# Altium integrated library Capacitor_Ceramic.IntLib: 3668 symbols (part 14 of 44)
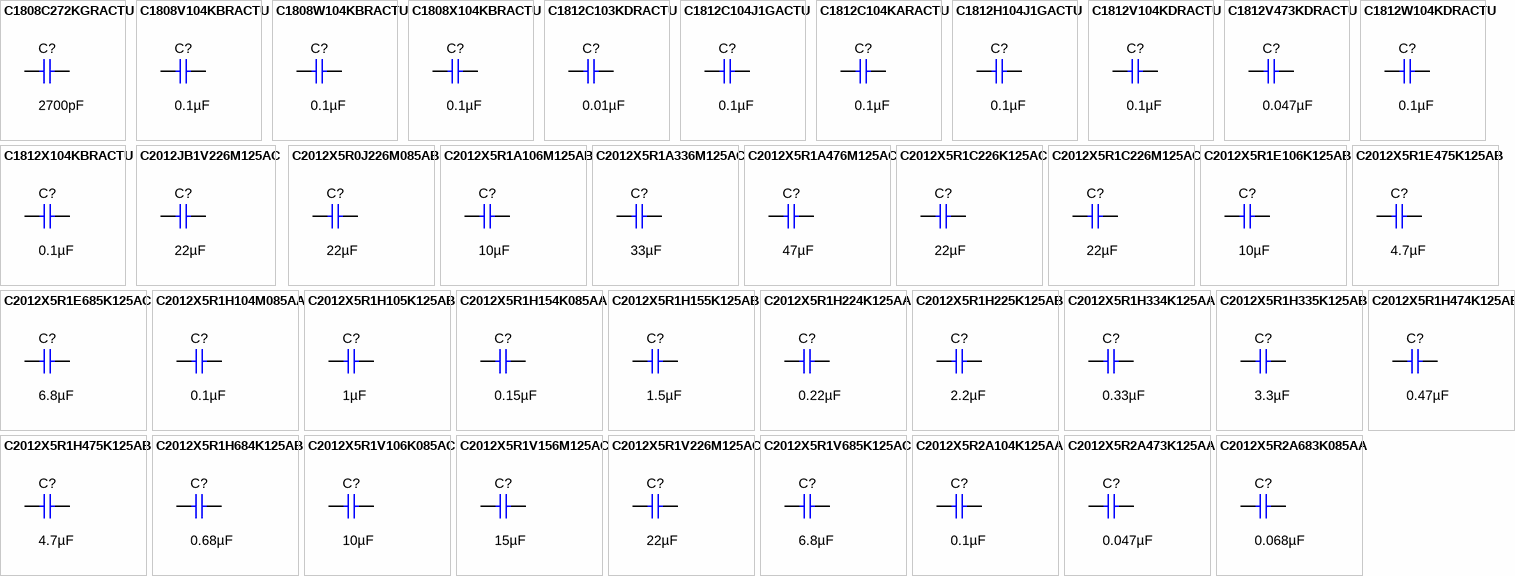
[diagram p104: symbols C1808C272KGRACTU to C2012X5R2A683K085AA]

## C1808V104KBRACTU
designator C?  ValueDisplayed: 0.1µF  (hidden comment: C1808V104KBRACTU)
CAP, CERM, 0.1 µF, 630 V,+/- 10%, X7R, 1808; Manufacturer: Kemet; Polarized: N; CompType: Capacitor; Value: 0.1uF; U/M: EA; Cap_F: 0.0000001; Tolerance_%: 10; VDC_V: 630; Value2: 630V; TaMin_C: -55; TaMax_C: 125; Cap_Case: 1808; SizeArea_mm2: 9; SizeAreaWB_mm2: 16.5; SizeX_mm: 4.5; SizeY_mm: 2; SizeZ_mm: 2.15; AEC Category: Q200; Green_Lifecycle: Not Set; Green_REACh: Incomplete
signal-integrity model Cap
simulation model Cap
footprint 1808_215
footprint 1808_215_M
footprint 1808_215_L
pins: 1, 2

## C1808W104KBRACTU
designator C?  ValueDisplayed: 0.1µF  (hidden comment: C1808W104KBRACTU)
CAP, CERM, 0.1 µF, 630 V,+/- 10%, X7R, 1808; Manufacturer: Kemet; Polarized: N; CompType: Capacitor; Value: 0.1uF; U/M: EA; Cap_F: 0.0000001; Tolerance_%: 10; VDC_V: 630; Value2: 630V; TaMin_C: -55; TaMax_C: 125; Cap_Case: 1808; SizeArea_mm2: 9; SizeAreaWB_mm2: 16.5; SizeX_mm: 4.5; SizeY_mm: 2; SizeZ_mm: 2.15; AEC Category: Q200; Green_Lifecycle: Not Set; Green_REACh: Incomplete
signal-integrity model Cap
simulation model Cap
footprint 1808_215
footprint 1808_215_M
footprint 1808_215_L
pins: 1, 2

## C1808X104KBRACTU
designator C?  ValueDisplayed: 0.1µF  (hidden comment: C1808X104KBRACTU)
CAP, CERM, 0.1 µF, 630 V,+/- 10%, X7R, 1808; Manufacturer: Kemet; Polarized: N; CompType: Capacitor; Value: 0.1uF; U/M: EA; Cap_F: 0.0000001; Tolerance_%: 10; VDC_V: 630; Value2: 630V; TaMin_C: -55; TaMax_C: 125; Cap_Case: 1808; SizeArea_mm2: 9; SizeAreaWB_mm2: 16.5; SizeX_mm: 4.5; SizeY_mm: 2; SizeZ_mm: 2.15; AEC Category: Q200; Green_Lifecycle: Not Set; Green_REACh: Incomplete
signal-integrity model Cap
simulation model Cap
footprint 1808_215
footprint 1808_215_M
footprint 1808_215_L
pins: 1, 2

## C1812C103KDRACTU
designator C?  ValueDisplayed: 0.01µF  (hidden comment: C1812C103KDRACTU)
CAP, CERM, 0.01 µF, 1000 V,+/- 10%, X7R, 1812; Manufacturer: Kemet; Polarized: N; CompType: Capacitor; Value: 0.01uF; U/M: EA; Cap_F: 0.00000001; Tolerance_%: 10; VDC_V: 1000; Value2: 1000V; TaMin_C: -55; TaMax_C: 125; Cap_Case: 1812; SizeArea_mm2: 14.4; SizeAreaWB_mm2: 23.1; SizeX_mm: 4.5; SizeY_mm: 3.2; SizeZ_mm: 1.8; AEC Category: Q200; Green_Lifecycle: Not Set; Green_REACh: Incomplete
signal-integrity model Cap
simulation model Cap
footprint 1812_180
pins: 1, 2

## C1812C104J1GACTU
designator C?  ValueDisplayed: 0.1µF  (hidden comment: C1812C104J1GACTU)
CAP, CERM, 0.1 µF, 100 V,+/- 5%, C0G/NP0, 1812; Manufacturer: Kemet; Polarized: N; CompType: Capacitor; Value: 0.1uF; U/M: EA; Cap_F: 0.0000001; Tolerance_%: 5; VDC_V: 100; Value2: 100V; TaMin_C: -55; TaMax_C: 125; Cap_Case: 1812; SizeArea_mm2: 14.4; SizeAreaWB_mm2: 23.1; SizeX_mm: 4.5; SizeY_mm: 3.2; SizeZ_mm: 1.35; AEC Category: Q200; Green_Lifecycle: Active; Green_REACh: Passed
signal-integrity model Cap
simulation model Cap
footprint 1812
footprint 1812M
footprint 1812L
footprint 1812_HV
pins: 1, 2

## C1812C104KARACTU
designator C?  ValueDisplayed: 0.1µF  (hidden comment: C1812C104KARACTU)
CAP, CERM, 0.1 µF, 250 V,+/- 10%, X7R, 1812; Manufacturer: Kemet; Polarized: N; CompType: Capacitor; Value: 0.1uF; U/M: EA; Cap_F: 0.0000001; Tolerance_%: 10; VDC_V: 250; Value2: 250V; TaMin_C: -55; TaMax_C: 125; Cap_Case: 1812; SizeArea_mm2: 14.4; SizeAreaWB_mm2: 23.1; SizeX_mm: 4.5; SizeY_mm: 3.2; SizeZ_mm: 1.35; AEC Category: Q200
signal-integrity model Cap
simulation model Cap
footprint 1812
footprint 1812M
footprint 1812L
footprint 1812_HV
pins: 1, 2

## C1812H104J1GACTU
designator C?  ValueDisplayed: 0.1µF  (hidden comment: C1812H104J1GACTU)
CAP, CERM, 0.1 µF, 100 V,+/- 5%, C0G/NP0, 1812; Manufacturer: Kemet; Polarized: N; CompType: Capacitor; Value: 0.1uF; U/M: EA; Cap_F: 0.0000001; Tolerance_%: 5; VDC_V: 100; Value2: 100V; TaMin_C: -55; TaMax_C: 200; Cap_Case: 1812; SizeArea_mm2: 14.4; SizeAreaWB_mm2: 23.1; SizeX_mm: 4.5; SizeY_mm: 3.2; SizeZ_mm: 1.35; AEC Category: Q200
signal-integrity model Cap
simulation model Cap
footprint 1812
footprint 1812M
footprint 1812L
footprint 1812_HV
pins: 1, 2

## C1812V104KDRACTU
designator C?  ValueDisplayed: 0.1µF  (hidden comment: C1812V104KDRACTU)
CAP, CERM, 0.1 µF, 1000 V,+/- 10%, X7R, 1812; Manufacturer: Kemet; Polarized: N; CompType: Capacitor; Value: 0.1uF; U/M: EA; Cap_F: 0.0000001; Tolerance_%: 10; VDC_V: 1000; Value2: 1000V; TaMin_C: -55; TaMax_C: 125; Cap_Case: 1812; SizeArea_mm2: 14.4; SizeAreaWB_mm2: 23.1; SizeX_mm: 4.5; SizeY_mm: 3.2; SizeZ_mm: 2.54; AEC Category: Q200; Green_Lifecycle: Not Set; Green_REACh: Incomplete
signal-integrity model Cap
simulation model Cap
footprint 1812_254
pins: 1, 2

## C1812V473KDRACTU
designator C?  ValueDisplayed: 0.047µF  (hidden comment: C1812V473KDRACTU)
CAP, CERM, 0.047 µF, 1000 V,+/- 10%, X7R, 1812; Manufacturer: Kemet; Polarized: N; CompType: Capacitor; Value: 0.047uF; U/M: EA; Cap_F: 0.000000047; Tolerance_%: 10; VDC_V: 1000; Value2: 1000V; TaMin_C: -55; TaMax_C: 125; Cap_Case: 1812; SizeArea_mm2: 14.4; SizeAreaWB_mm2: 23.1; SizeX_mm: 4.5; SizeY_mm: 3.2; SizeZ_mm: 1.35; AEC Category: Q200
signal-integrity model Cap
simulation model Cap
footprint 1812
footprint 1812M
footprint 1812L
footprint 1812_HV
pins: 1, 2

## C1812W104KDRACTU
designator C?  ValueDisplayed: 0.1µF  (hidden comment: C1812W104KDRACTU)
CAP, CERM, 0.1 µF, 1000 V,+/- 10%, X7R, 1812; Manufacturer: Kemet; Polarized: N; CompType: Capacitor; Value: 0.1uF; U/M: EA; Cap_F: 0.0000001; Tolerance_%: 10; VDC_V: 1000; Value2: 1000V; TaMin_C: -55; TaMax_C: 125; Cap_Case: 1812; SizeArea_mm2: 14.4; SizeAreaWB_mm2: 23.1; SizeX_mm: 4.5; SizeY_mm: 3.2; SizeZ_mm: 2.54; AEC Category: Q200; Green_Lifecycle: Active; Green_REACh: Passed
signal-integrity model Cap
simulation model Cap
footprint 1812_254
pins: 1, 2

## C1812X104KBRACTU
designator C?  ValueDisplayed: 0.1µF  (hidden comment: C1812X104KBRACTU)
CAP, CERM, 0.1 µF, 630 V,+/- 10%, X7R, 1812; Manufacturer: Kemet; Polarized: N; CompType: Capacitor; Value: 0.1uF; U/M: EA; Cap_F: 0.0000001; Tolerance_%: 10; VDC_V: 630; Value2: 630V; TaMin_C: -55; TaMax_C: 125; Cap_Case: 1812; SizeArea_mm2: 14.4; SizeAreaWB_mm2: 23.1; SizeX_mm: 4.5; SizeY_mm: 3.2; SizeZ_mm: 2.54; AEC Category: Q200; Green_Lifecycle: Not Set; Green_REACh: Incomplete
signal-integrity model Cap
simulation model Cap
footprint 1812_254
pins: 1, 2

## C2012JB1V226M125AC
designator C?  ValueDisplayed: 22µF  (hidden comment: C2012JB1V226M125AC)
CAP, CERM, 22 µF, 35 V,+/- 20%, JB, 0805; Manufacturer: TDK; Polarized: N; CompType: Capacitor; Value: 22uF; U/M: EA; Cap_F: 0.000022; Tolerance_%: 20; VDC_V: 35; Value2: 35V; TaMin_C: -25; TaMax_C: 85; Cap_Case: 0805; SizeArea_mm2: 2.5; SizeAreaWB_mm2: 6.75; SizeX_mm: 2; SizeY_mm: 1.25; SizeZ_mm: 1.45; AEC Category: Q200; Green_Lifecycle: Active; Green_REACh: Passed
signal-integrity model Cap
simulation model Cap
footprint 0805_HV
footprint 0805_HV1
footprint 0805
footprint 0805M
footprint 0805L
pins: 1, 2

## C2012X5R0J226M085AB
designator C?  ValueDisplayed: 22µF  (hidden comment: C2012X5R0J226M085AB)
CAP, CERM, 22 µF, 6.3 V,+/- 20%, X5R, 0805; Manufacturer: TDK; Polarized: N; CompType: Capacitor; Value: 22uF; U/M: EA; Cap_F: 0.000022; Tolerance_%: 20; VDC_V: 6.3; Value2: 6.3V; TaMin_C: -55; TaMax_C: 85; Cap_Case: 0805; SizeArea_mm2: 2.5; SizeAreaWB_mm2: 6.75; SizeX_mm: 2; SizeY_mm: 1.25; SizeZ_mm: 1.45; AEC Category: Q200
signal-integrity model Cap
simulation model Cap
footprint 0805_HV
footprint 0805_HV1
footprint 0805
footprint 0805M
footprint 0805L
pins: 1, 2

## C2012X5R1A106M125AB
designator C?  ValueDisplayed: 10µF  (hidden comment: C2012X5R1A106M125AB)
CAP, CERM, 10 µF, 10 V,+/- 20%, X5R, 0805; Manufacturer: TDK; Polarized: N; CompType: Capacitor; Value: 10uF; U/M: EA; Cap_F: 0.00001; Tolerance_%: 20; VDC_V: 10; Value2: 10V; TaMin_C: -55; TaMax_C: 85; Cap_Case: 0805; SizeArea_mm2: 2.5; SizeAreaWB_mm2: 6.75; SizeX_mm: 2; SizeY_mm: 1.25; SizeZ_mm: 1.5; AEC Category: Q200; Green_Lifecycle: EOL; Green_REACh: Passed
signal-integrity model Cap
simulation model Cap
footprint 0805_150
pins: 1, 2

## C2012X5R1A336M125AC
designator C?  ValueDisplayed: 33µF  (hidden comment: C2012X5R1A336M125AC)
CAP, CERM, 33 µF, 10 V,+/- 20%, X5R, 0805; Manufacturer: TDK; Polarized: N; CompType: Capacitor; Value: 33uF; U/M: EA; Cap_F: 0.000033; Tolerance_%: 20; ESR_ohm: 0.001694; Value1: 0.001694 ohm; VDC_V: 10; Value2: 10V; IRMS_A: 5.01281; TaMin_C: -55; TaMax_C: 85; Cap_Case: 0805; SizeArea_mm2: 2.5; SizeAreaWB_mm2: 6.75; SizeX_mm: 2; SizeY_mm: 1.25; SizeZ_mm: 1.45; AEC Category: Q200; Green_Lifecycle: Active; Green_REACh: Passed
signal-integrity model Cap
simulation model Cap
footprint 0805_HV
footprint 0805_HV1
footprint 0805
footprint 0805M
footprint 0805L
pins: 1, 2

## C2012X5R1A476M125AC
designator C?  ValueDisplayed: 47µF  (hidden comment: C2012X5R1A476M125AC)
CAP, CERM, 47 µF, 10 V,+/- 20%, X5R, 0805; Manufacturer: TDK; Polarized: N; CompType: Capacitor; Value: 47uF; U/M: EA; Cap_F: 0.000047; Tolerance_%: 20; ESR_ohm: 0.00294; Value1: 0.00294 ohm; VDC_V: 10; Value2: 10V; IRMS_A: 3.80451; TaMin_C: -55; TaMax_C: 85; Cap_Case: 0805; SizeArea_mm2: 2.5; SizeAreaWB_mm2: 6.75; SizeX_mm: 2; SizeY_mm: 1.25; SizeZ_mm: 1.45; AEC Category: Q200; Green_Lifecycle: Active; Green_REACh: Passed
signal-integrity model Cap
simulation model Cap
footprint 0805_HV
footprint 0805_HV1
footprint 0805
footprint 0805M
footprint 0805L
pins: 1, 2

## C2012X5R1C226K125AC
designator C?  ValueDisplayed: 22µF  (hidden comment: C2012X5R1C226K125AC)
CAP, CERM, 22 µF, 16 V,+/- 10%, X5R, 0805; Manufacturer: TDK; Polarized: N; CompType: Capacitor; Value: 22uF; U/M: EA; Cap_F: 0.000022; Tolerance_%: 10; VDC_V: 16; Value2: 16V; TaMin_C: -55; TaMax_C: 85; Cap_Case: 0805; SizeArea_mm2: 2.5; SizeAreaWB_mm2: 6.75; SizeX_mm: 2; SizeY_mm: 1.25; SizeZ_mm: 1.45; AEC Category: Q200; Green_Lifecycle: Active; Green_REACh: Passed
signal-integrity model Cap
simulation model Cap
footprint 0805_HV
footprint 0805_HV1
footprint 0805
footprint 0805M
footprint 0805L
pins: 1, 2

## C2012X5R1C226M125AC
designator C?  ValueDisplayed: 22µF  (hidden comment: C2012X5R1C226M125AC)
CAP, CERM, 22 µF, 16 V,+/- 20%, X5R, 0805; Manufacturer: TDK; Polarized: N; CompType: Capacitor; Value: 22uF; U/M: EA; Cap_F: 0.000022; Tolerance_%: 20; VDC_V: 16; Value2: 16V; TaMin_C: -55; TaMax_C: 85; Cap_Case: 0805; SizeArea_mm2: 2.5; SizeAreaWB_mm2: 6.75; SizeX_mm: 2; SizeY_mm: 1.25; SizeZ_mm: 1.45; AEC Category: Q200; Green_Lifecycle: Active; Green_REACh: Passed
signal-integrity model Cap
simulation model Cap
footprint 0805_HV
footprint 0805_HV1
footprint 0805
footprint 0805M
footprint 0805L
pins: 1, 2

## C2012X5R1E106K125AB
designator C?  ValueDisplayed: 10µF  (hidden comment: C2012X5R1E106K125AB)
CAP, CERM, 10 µF, 25 V,+/- 10%, X5R, 0805; Manufacturer: TDK; Polarized: N; CompType: Capacitor; Value: 10uF; U/M: EA; Cap_F: 0.00001; Tolerance_%: 10; VDC_V: 25; Value2: 25V; TaMin_C: -55; TaMax_C: 85; Cap_Case: 0805; SizeArea_mm2: 2.5; SizeAreaWB_mm2: 6.75; SizeX_mm: 2; SizeY_mm: 1.25; SizeZ_mm: 1.45; AEC Category: Q200; Green_Lifecycle: Active; Green_REACh: Passed
signal-integrity model Cap
simulation model Cap
footprint 0805_HV
footprint 0805_HV1
footprint 0805
footprint 0805M
footprint 0805L
pins: 1, 2

## C2012X5R1E475K125AB
designator C?  ValueDisplayed: 4.7µF  (hidden comment: C2012X5R1E475K125AB)
CAP, CERM, 4.7 µF, 25 V,+/- 10%, X5R, 0805; Manufacturer: TDK; Polarized: N; CompType: Capacitor; Value: 4.7uF; U/M: EA; Cap_F: 0.0000047; Tolerance_%: 10; VDC_V: 25; Value2: 25V; TaMin_C: -55; TaMax_C: 85; Cap_Case: 0805; SizeArea_mm2: 2.5; SizeAreaWB_mm2: 6.75; SizeX_mm: 2; SizeY_mm: 1.25; SizeZ_mm: 1.45; AEC Category: Q200; Green_Lifecycle: Active; Green_REACh: Passed
signal-integrity model Cap
simulation model Cap
footprint 0805_HV
footprint 0805_HV1
footprint 0805
footprint 0805M
footprint 0805L
pins: 1, 2

## C2012X5R1E685K125AC
designator C?  ValueDisplayed: 6.8µF  (hidden comment: C2012X5R1E685K125AC)
CAP, CERM, 6.8 µF, 25 V,+/- 10%, X5R, 0805; Manufacturer: TDK; Polarized: N; CompType: Capacitor; Value: 6.8uF; U/M: EA; Cap_F: 0.0000068; Tolerance_%: 10; VDC_V: 25; Value2: 25V; TaMin_C: -55; TaMax_C: 85; Cap_Case: 0805; SizeArea_mm2: 2.5; SizeAreaWB_mm2: 6.75; SizeX_mm: 2; SizeY_mm: 1.25; SizeZ_mm: 1.45; AEC Category: Q200; Green_Lifecycle: Not Set; Green_REACh: Incomplete
signal-integrity model Cap
simulation model Cap
footprint 0805_HV
footprint 0805_HV1
footprint 0805
footprint 0805M
footprint 0805L
pins: 1, 2

## C2012X5R1H104M085AA
designator C?  ValueDisplayed: 0.1µF  (hidden comment: C2012X5R1H104M085AA)
CAP, CERM, 0.1 µF, 50 V,+/- 20%, X5R, 0805; Manufacturer: TDK; Polarized: N; CompType: Capacitor; Value: 0.1uF; U/M: EA; Cap_F: 0.0000001; Tolerance_%: 20; ESR_ohm: 0.02619; Value1: 0.02619 ohm; VDC_V: 50; Value2: 50V; IRMS_A: 1.29514; TaMin_C: -55; TaMax_C: 85; Cap_Case: 0805; SizeArea_mm2: 2.5; SizeAreaWB_mm2: 6.75; SizeX_mm: 2; SizeY_mm: 1.25; SizeZ_mm: 1.45; AEC Category: Q200; Green_Lifecycle: NRND; Green_REACh: Passed
signal-integrity model Cap
simulation model Cap
footprint 0805_HV
footprint 0805_HV1
footprint 0805
footprint 0805M
footprint 0805L
pins: 1, 2

## C2012X5R1H105K125AB
designator C?  ValueDisplayed: 1µF  (hidden comment: C2012X5R1H105K125AB)
CAP, CERM, 1 µF, 50 V,+/- 10%, X5R, 0805; Manufacturer: TDK; Polarized: N; CompType: Capacitor; Value: 1uF; U/M: EA; Cap_F: 0.000001; Tolerance_%: 10; ESR_ohm: 0.008782; Value1: 0.008782 ohm; VDC_V: 50; Value2: 50V; IRMS_A: 2.20488; TaMin_C: -55; TaMax_C: 85; Cap_Case: 0805; SizeArea_mm2: 2.5; SizeAreaWB_mm2: 6.75; SizeX_mm: 2; SizeY_mm: 1.25; SizeZ_mm: 1.45; AEC Category: Q200
signal-integrity model Cap
simulation model Cap
footprint 0805_HV
footprint 0805_HV1
footprint 0805
footprint 0805M
footprint 0805L
pins: 1, 2

## C2012X5R1H154K085AA
designator C?  ValueDisplayed: 0.15µF  (hidden comment: C2012X5R1H154K085AA)
CAP, CERM, 0.15 µF, 50 V,+/- 10%, X5R, 0805; Manufacturer: TDK; Polarized: N; CompType: Capacitor; Value: 0.15uF; U/M: EA; Cap_F: 0.00000015; Tolerance_%: 10; ESR_ohm: 0.023723; Value1: 0.023723 ohm; VDC_V: 50; Value2: 50V; IRMS_A: 1.35424; TaMin_C: -55; TaMax_C: 85; Cap_Case: 0805; SizeArea_mm2: 2.5; SizeAreaWB_mm2: 6.75; SizeX_mm: 2; SizeY_mm: 1.25; SizeZ_mm: 1.45; AEC Category: Q200
signal-integrity model Cap
simulation model Cap
footprint 0805_HV
footprint 0805_HV1
footprint 0805
footprint 0805M
footprint 0805L
pins: 1, 2

## C2012X5R1H155K125AB
designator C?  ValueDisplayed: 1.5µF  (hidden comment: C2012X5R1H155K125AB)
CAP, CERM, 1.5 µF, 50 V,+/- 10%, X5R, 0805; Manufacturer: TDK; Polarized: N; CompType: Capacitor; Value: 1.5uF; U/M: EA; Cap_F: 0.0000015; Tolerance_%: 10; ESR_ohm: 0.004574; Value1: 0.004574 ohm; VDC_V: 50; Value2: 50V; IRMS_A: 3.05357; TaMin_C: -55; TaMax_C: 85; Cap_Case: 0805; SizeArea_mm2: 2.5; SizeAreaWB_mm2: 6.75; SizeX_mm: 2; SizeY_mm: 1.25; SizeZ_mm: 1.45; AEC Category: Q200
signal-integrity model Cap
simulation model Cap
footprint 0805_HV
footprint 0805_HV1
footprint 0805
footprint 0805M
footprint 0805L
pins: 1, 2

## C2012X5R1H224K125AA
designator C?  ValueDisplayed: 0.22µF  (hidden comment: C2012X5R1H224K125AA)
CAP, CERM, 0.22 µF, 50 V,+/- 10%, X5R, 0805; Manufacturer: TDK; Polarized: N; CompType: Capacitor; Value: 0.22uF; U/M: EA; Cap_F: 0.00000022; Tolerance_%: 10; ESR_ohm: 0.016949; Value1: 0.016949 ohm; VDC_V: 50; Value2: 50V; IRMS_A: 1.59611; TaMin_C: -55; TaMax_C: 85; Cap_Case: 0805; SizeArea_mm2: 2.5; SizeAreaWB_mm2: 6.75; SizeX_mm: 2; SizeY_mm: 1.25; SizeZ_mm: 1.45; AEC Category: Q200; Green_Lifecycle: NRND; Green_REACh: Passed
signal-integrity model Cap
simulation model Cap
footprint 0805_HV
footprint 0805_HV1
footprint 0805
footprint 0805M
footprint 0805L
pins: 1, 2

## C2012X5R1H225K125AB
designator C?  ValueDisplayed: 2.2µF  (hidden comment: C2012X5R1H225K125AB)
CAP, CERM, 2.2 µF, 50 V,+/- 10%, X5R, 0805; Manufacturer: TDK; Polarized: N; CompType: Capacitor; Value: 2.2uF; U/M: EA; Cap_F: 0.0000022; Tolerance_%: 10; ESR_ohm: 0.00366; Value1: 0.00366 ohm; VDC_V: 50; Value2: 50V; IRMS_A: 3.41207; TaMin_C: -55; TaMax_C: 85; Cap_Case: 0805; SizeArea_mm2: 2.5; SizeAreaWB_mm2: 6.75; SizeX_mm: 2; SizeY_mm: 1.25; SizeZ_mm: 1.45; AEC Category: Q200; Green_Lifecycle: Active; Green_REACh: Passed
signal-integrity model Cap
simulation model Cap
footprint 0805_HV
footprint 0805_HV1
footprint 0805
footprint 0805M
footprint 0805L
pins: 1, 2

## C2012X5R1H334K125AA
designator C?  ValueDisplayed: 0.33µF  (hidden comment: C2012X5R1H334K125AA)
CAP, CERM, 0.33 µF, 50 V,+/- 10%, X5R, 0805; Manufacturer: TDK; Polarized: N; CompType: Capacitor; Value: 0.33uF; U/M: EA; Cap_F: 0.00000033; Tolerance_%: 10; ESR_ohm: 0.012274; Value1: 0.012274 ohm; VDC_V: 50; Value2: 50V; IRMS_A: 1.87147; TaMin_C: -55; TaMax_C: 85; Cap_Case: 0805; SizeArea_mm2: 2.5; SizeAreaWB_mm2: 6.75; SizeX_mm: 2; SizeY_mm: 1.25; SizeZ_mm: 1.45; AEC Category: Q200
signal-integrity model Cap
simulation model Cap
footprint 0805_HV
footprint 0805_HV1
footprint 0805
footprint 0805M
footprint 0805L
pins: 1, 2

## C2012X5R1H335K125AB
designator C?  ValueDisplayed: 3.3µF  (hidden comment: C2012X5R1H335K125AB)
CAP, CERM, 3.3 µF, 50 V,+/- 10%, X5R, 0805; Manufacturer: TDK; Polarized: N; CompType: Capacitor; Value: 3.3uF; U/M: EA; Cap_F: 0.0000033; Tolerance_%: 10; ESR_ohm: 0.002798; Value1: 0.002798 ohm; VDC_V: 50; Value2: 50V; IRMS_A: 3.90156; TaMin_C: -55; TaMax_C: 85; Cap_Case: 0805; SizeArea_mm2: 2.5; SizeAreaWB_mm2: 6.75; SizeX_mm: 2; SizeY_mm: 1.25; SizeZ_mm: 1.45; AEC Category: Q200
signal-integrity model Cap
simulation model Cap
footprint 0805_HV
footprint 0805_HV1
footprint 0805
footprint 0805M
footprint 0805L
pins: 1, 2

## C2012X5R1H474K125AB
designator C?  ValueDisplayed: 0.47µF  (hidden comment: C2012X5R1H474K125AB)
CAP, CERM, 0.47 µF, 50 V,+/- 10%, X5R, 0805; Manufacturer: TDK; Polarized: N; CompType: Capacitor; Value: 0.47uF; U/M: EA; Cap_F: 0.00000047; Tolerance_%: 10; ESR_ohm: 0.022012; Value1: 0.022012 ohm; VDC_V: 50; Value2: 50V; IRMS_A: 1.39566; TaMin_C: -55; TaMax_C: 85; Cap_Case: 0805; SizeArea_mm2: 2.5; SizeAreaWB_mm2: 6.75; SizeX_mm: 2; SizeY_mm: 1.25; SizeZ_mm: 1.45; AEC Category: Q200
signal-integrity model Cap
simulation model Cap
footprint 0805_HV
footprint 0805_HV1
footprint 0805
footprint 0805M
footprint 0805L
pins: 1, 2

## C2012X5R1H475K125AB
designator C?  ValueDisplayed: 4.7µF  (hidden comment: C2012X5R1H475K125AB)
CAP, CERM, 4.7 µF, 50 V,+/- 10%, X5R, 0805; Manufacturer: TDK; Polarized: N; CompType: Capacitor; Value: 4.7uF; U/M: EA; Cap_F: 0.0000047; Tolerance_%: 10; ESR_ohm: 0.002346; Value1: 0.002346 ohm; VDC_V: 50; Value2: 50V; IRMS_A: 4.26021; TaMin_C: -55; TaMax_C: 85; Cap_Case: 0805; SizeArea_mm2: 2.5; SizeAreaWB_mm2: 6.75; SizeX_mm: 2; SizeY_mm: 1.25; SizeZ_mm: 1.45; AEC Category: Q200; Green_Lifecycle: Active; Green_REACh: Passed
signal-integrity model Cap
simulation model Cap
footprint 0805_HV
footprint 0805_HV1
footprint 0805
footprint 0805M
footprint 0805L
pins: 1, 2

## C2012X5R1H684K125AB
designator C?  ValueDisplayed: 0.68µF  (hidden comment: C2012X5R1H684K125AB)
CAP, CERM, 0.68 µF, 50 V,+/- 10%, X5R, 0805; Manufacturer: TDK; Polarized: N; CompType: Capacitor; Value: 0.68uF; U/M: EA; Cap_F: 0.00000068; Tolerance_%: 10; ESR_ohm: 0.011711; Value1: 0.011711 ohm; VDC_V: 50; Value2: 50V; IRMS_A: 1.91098; TaMin_C: -55; TaMax_C: 85; Cap_Case: 0805; SizeArea_mm2: 2.5; SizeAreaWB_mm2: 6.75; SizeX_mm: 2; SizeY_mm: 1.25; SizeZ_mm: 1.45; AEC Category: Q200
signal-integrity model Cap
simulation model Cap
footprint 0805_HV
footprint 0805_HV1
footprint 0805
footprint 0805M
footprint 0805L
pins: 1, 2

## C2012X5R1V106K085AC
designator C?  ValueDisplayed: 10µF  (hidden comment: C2012X5R1V106K085AC)
CAP, CERM, 10 µF, 35 V,+/- 10%, X5R, 0805; Manufacturer: TDK; Polarized: N; CompType: Capacitor; Value: 10uF; U/M: EA; Cap_F: 0.00001; Tolerance_%: 10; ESR_ohm: 0.002818; Value1: 0.002818 ohm; VDC_V: 35; Value2: 35V; IRMS_A: 3.88676; TaMin_C: -55; TaMax_C: 85; Cap_Case: 0805; SizeArea_mm2: 2.5; SizeAreaWB_mm2: 6.75; SizeX_mm: 2; SizeY_mm: 1.25; SizeZ_mm: 1.45; AEC Category: Q200; Green_Lifecycle: Active; Green_REACh: Passed
signal-integrity model Cap
simulation model Cap
footprint 0805_HV
footprint 0805_HV1
footprint 0805
footprint 0805M
footprint 0805L
pins: 1, 2

## C2012X5R1V156M125AC
designator C?  ValueDisplayed: 15µF  (hidden comment: C2012X5R1V156M125AC)
CAP, CERM, 15 µF, 35 V,+/- 20%, X5R, 0805; Manufacturer: TDK; Polarized: N; CompType: Capacitor; Value: 15uF; U/M: EA; Cap_F: 0.000015; Tolerance_%: 20; ESR_ohm: 0.001669; Value1: 0.001669 ohm; VDC_V: 35; Value2: 35V; IRMS_A: 5.04984; TaMin_C: -55; TaMax_C: 85; Cap_Case: 0805; SizeArea_mm2: 2.5; SizeAreaWB_mm2: 6.75; SizeX_mm: 2; SizeY_mm: 1.25; SizeZ_mm: 1.45; AEC Category: Q200
signal-integrity model Cap
simulation model Cap
footprint 0805_HV
footprint 0805_HV1
footprint 0805
footprint 0805M
footprint 0805L
pins: 1, 2

## C2012X5R1V226M125AC
designator C?  ValueDisplayed: 22µF  (hidden comment: C2012X5R1V226M125AC)
CAP, CERM, 22 µF, 35 V,+/- 20%, X5R, 0805; Manufacturer: TDK; Polarized: N; CompType: Capacitor; Value: 22uF; U/M: EA; Cap_F: 0.000022; Tolerance_%: 20; ESR_ohm: 0.00205; Value1: 0.00205 ohm; VDC_V: 35; Value2: 35V; IRMS_A: 4.55587; TaMin_C: -55; TaMax_C: 85; Cap_Case: 0805; SizeArea_mm2: 2.5; SizeAreaWB_mm2: 6.75; SizeX_mm: 2; SizeY_mm: 1.25; SizeZ_mm: 1.45; AEC Category: Q200; Green_Lifecycle: Active; Green_REACh: Passed
signal-integrity model Cap
simulation model Cap
footprint 0805_HV
footprint 0805_HV1
footprint 0805
footprint 0805M
footprint 0805L
pins: 1, 2

## C2012X5R1V685K125AC
designator C?  ValueDisplayed: 6.8µF  (hidden comment: C2012X5R1V685K125AC)
CAP, CERM, 6.8 µF, 35 V,+/- 10%, X5R, 0805; Manufacturer: TDK; Polarized: N; CompType: Capacitor; Value: 6.8uF; U/M: EA; Cap_F: 0.0000068; Tolerance_%: 10; ESR_ohm: 0.003795; Value1: 0.003795 ohm; VDC_V: 35; Value2: 35V; IRMS_A: 3.34931; TaMin_C: -55; TaMax_C: 85; Cap_Case: 0805; SizeArea_mm2: 2.5; SizeAreaWB_mm2: 6.75; SizeX_mm: 2; SizeY_mm: 1.25; SizeZ_mm: 1.45; AEC Category: Q200
signal-integrity model Cap
simulation model Cap
footprint 0805_HV
footprint 0805_HV1
footprint 0805
footprint 0805M
footprint 0805L
pins: 1, 2

## C2012X5R2A104K125AA
designator C?  ValueDisplayed: 0.1µF  (hidden comment: C2012X5R2A104K125AA)
CAP, CERM, 0.1 µF, 100 V,+/- 10%, X5R, 0805; Manufacturer: TDK; Polarized: N; CompType: Capacitor; Value: 0.1uF; U/M: EA; Cap_F: 0.0000001; Tolerance_%: 10; ESR_ohm: 0.020726; Value1: 0.020726 ohm; VDC_V: 100; Value2: 100V; IRMS_A: 1.456; TaMin_C: -55; TaMax_C: 85; Cap_Case: 0805; SizeArea_mm2: 2.5; SizeAreaWB_mm2: 6.75; SizeX_mm: 2; SizeY_mm: 1.25; SizeZ_mm: 1.45; AEC Category: Q200
signal-integrity model Cap
simulation model Cap
footprint 0805_HV
footprint 0805_HV1
footprint 0805
footprint 0805M
footprint 0805L
pins: 1, 2

## C2012X5R2A473K125AA
designator C?  ValueDisplayed: 0.047µF  (hidden comment: C2012X5R2A473K125AA)
CAP, CERM, 0.047 µF, 100 V,+/- 10%, X5R, 0805; Manufacturer: TDK; Polarized: N; CompType: Capacitor; Value: 0.047uF; U/M: EA; Cap_F: 0.000000047; Tolerance_%: 10; ESR_ohm: 0.049089; Value1: 0.049089 ohm; VDC_V: 100; Value2: 100V; IRMS_A: 0.963171; TaMin_C: -55; TaMax_C: 85; Cap_Case: 0805; SizeArea_mm2: 2.5; SizeAreaWB_mm2: 6.75; SizeX_mm: 2; SizeY_mm: 1.25; SizeZ_mm: 1.45; AEC Category: Q200
signal-integrity model Cap
simulation model Cap
footprint 0805_HV
footprint 0805_HV1
footprint 0805
footprint 0805M
footprint 0805L
pins: 1, 2

## C2012X5R2A683K085AA
designator C?  ValueDisplayed: 0.068µF  (hidden comment: C2012X5R2A683K085AA)
CAP, CERM, 0.068 µF, 100 V,+/- 10%, X5R, 0805; Manufacturer: TDK; Polarized: N; CompType: Capacitor; Value: 0.068uF; U/M: EA; Cap_F: 0.000000068; Tolerance_%: 10; ESR_ohm: 0.027836; Value1: 0.027836 ohm; VDC_V: 100; Value2: 100V; IRMS_A: 1.26527; TaMin_C: -55; TaMax_C: 85; Cap_Case: 0805; SizeArea_mm2: 2.5; SizeAreaWB_mm2: 6.75; SizeX_mm: 2; SizeY_mm: 1.25; SizeZ_mm: 1.45; AEC Category: Q200
signal-integrity model Cap
simulation model Cap
footprint 0805_HV
footprint 0805_HV1
footprint 0805
footprint 0805M
footprint 0805L
pins: 1, 2

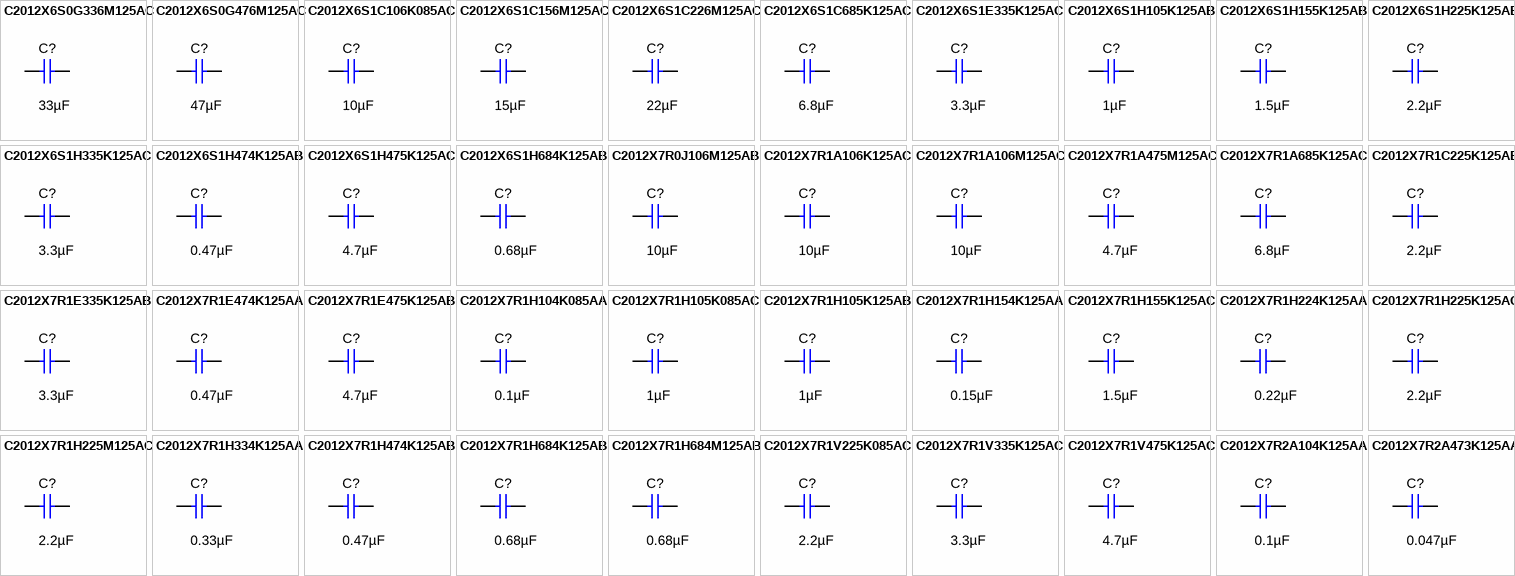
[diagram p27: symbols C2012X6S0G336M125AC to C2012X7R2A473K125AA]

## C2012X6S0G336M125AC
designator C?  ValueDisplayed: 33µF  (hidden comment: C2012X6S0G336M125AC)
CAP, CERM, 33 µF, 4 V,+/- 20%, X6S, 0805; Manufacturer: TDK; Polarized: N; CompType: Capacitor; Value: 33uF; U/M: EA; Cap_F: 0.000033; Tolerance_%: 20; ESR_ohm: 0.001518; Value1: 0.001518 ohm; VDC_V: 4; Value2: 4V; IRMS_A: 5.29465; TaMin_C: -55; TaMax_C: 105; Cap_Case: 0805; SizeArea_mm2: 2.5; SizeAreaWB_mm2: 6.75; SizeX_mm: 2; SizeY_mm: 1.25; SizeZ_mm: 1.45; AEC Category: Q200
signal-integrity model Cap
simulation model Cap
footprint 0805_HV
footprint 0805_HV1
footprint 0805
footprint 0805M
footprint 0805L
pins: 1, 2

## C2012X6S0G476M125AC
designator C?  ValueDisplayed: 47µF  (hidden comment: C2012X6S0G476M125AC)
CAP, CERM, 47 µF, 4 V,+/- 20%, X6S, 0805; Manufacturer: TDK; Polarized: N; CompType: Capacitor; Value: 47uF; U/M: EA; Cap_F: 0.000047; Tolerance_%: 20; VDC_V: 4; Value2: 4V; TaMin_C: -55; TaMax_C: 105; Cap_Case: 0805; SizeArea_mm2: 2.5; SizeAreaWB_mm2: 6.75; SizeX_mm: 2; SizeY_mm: 1.25; SizeZ_mm: 1.45; AEC Category: Q200
signal-integrity model Cap
simulation model Cap
footprint 0805_HV
footprint 0805_HV1
footprint 0805
footprint 0805M
footprint 0805L
pins: 1, 2

## C2012X6S1C106K085AC
designator C?  ValueDisplayed: 10µF  (hidden comment: C2012X6S1C106K085AC)
CAP, CERM, 10 µF, 16 V,+/- 10%, X6S, 0805; Manufacturer: TDK; Polarized: N; CompType: Capacitor; Value: 10uF; U/M: EA; Cap_F: 0.00001; Tolerance_%: 10; ESR_ohm: 0.002818; Value1: 0.002818 ohm; VDC_V: 16; Value2: 16V; IRMS_A: 3.88676; TaMin_C: -55; TaMax_C: 105; Cap_Case: 0805; SizeArea_mm2: 2.5; SizeAreaWB_mm2: 6.75; SizeX_mm: 2; SizeY_mm: 1.25; SizeZ_mm: 1.45; AEC Category: Q200
signal-integrity model Cap
simulation model Cap
footprint 0805_HV
footprint 0805_HV1
footprint 0805
footprint 0805M
footprint 0805L
pins: 1, 2

## C2012X6S1C156M125AC
designator C?  ValueDisplayed: 15µF  (hidden comment: C2012X6S1C156M125AC)
CAP, CERM, 15 µF, 16 V,+/- 20%, X6S, 0805; Manufacturer: TDK; Polarized: N; CompType: Capacitor; Value: 15uF; U/M: EA; Cap_F: 0.000015; Tolerance_%: 20; ESR_ohm: 0.001669; Value1: 0.001669 ohm; VDC_V: 16; Value2: 16V; IRMS_A: 5.04984; TaMin_C: -55; TaMax_C: 105; Cap_Case: 0805; SizeArea_mm2: 2.5; SizeAreaWB_mm2: 6.75; SizeX_mm: 2; SizeY_mm: 1.25; SizeZ_mm: 1.45; AEC Category: Q200
signal-integrity model Cap
simulation model Cap
footprint 0805_HV
footprint 0805_HV1
footprint 0805
footprint 0805M
footprint 0805L
pins: 1, 2

## C2012X6S1C226M125AC
designator C?  ValueDisplayed: 22µF  (hidden comment: C2012X6S1C226M125AC)
CAP, CERM, 22 µF, 16 V,+/- 20%, X6S, 0805; Manufacturer: TDK; Polarized: N; CompType: Capacitor; Value: 22uF; U/M: EA; Cap_F: 0.000022; Tolerance_%: 20; ESR_ohm: 0.00205; Value1: 0.00205 ohm; VDC_V: 16; Value2: 16V; IRMS_A: 4.55587; TaMin_C: -55; TaMax_C: 105; Cap_Case: 0805; SizeArea_mm2: 2.5; SizeAreaWB_mm2: 6.75; SizeX_mm: 2; SizeY_mm: 1.25; SizeZ_mm: 1.45; AEC Category: Q200
signal-integrity model Cap
simulation model Cap
footprint 0805_HV
footprint 0805_HV1
footprint 0805
footprint 0805M
footprint 0805L
pins: 1, 2

## C2012X6S1C685K125AC
designator C?  ValueDisplayed: 6.8µF  (hidden comment: C2012X6S1C685K125AC)
CAP, CERM, 6.8 µF, 16 V,+/- 10%, X6S, 0805; Manufacturer: TDK; Polarized: N; CompType: Capacitor; Value: 6.8uF; U/M: EA; Cap_F: 0.0000068; Tolerance_%: 10; ESR_ohm: 0.003795; Value1: 0.003795 ohm; VDC_V: 16; Value2: 16V; IRMS_A: 3.34931; TaMin_C: -55; TaMax_C: 105; Cap_Case: 0805; SizeArea_mm2: 2.5; SizeAreaWB_mm2: 6.75; SizeX_mm: 2; SizeY_mm: 1.25; SizeZ_mm: 1.45; AEC Category: Q200
signal-integrity model Cap
simulation model Cap
footprint 0805_HV
footprint 0805_HV1
footprint 0805
footprint 0805M
footprint 0805L
pins: 1, 2

## C2012X6S1E335K125AC
designator C?  ValueDisplayed: 3.3µF  (hidden comment: C2012X6S1E335K125AC)
CAP, CERM, 3.3 µF, 25 V,+/- 10%, X6S, 0805; Manufacturer: TDK; Polarized: N; CompType: Capacitor; Value: 3.3uF; U/M: EA; Cap_F: 0.0000033; Tolerance_%: 10; VDC_V: 25; Value2: 25V; TaMin_C: -55; TaMax_C: 105; Cap_Case: 0805; SizeArea_mm2: 2.5; SizeAreaWB_mm2: 6.75; SizeX_mm: 2; SizeY_mm: 1.25; SizeZ_mm: 1.45; AEC Category: Q200; Green_Lifecycle: Not Set; Green_REACh: Incomplete
signal-integrity model Cap
simulation model Cap
footprint 0805_HV
footprint 0805_HV1
footprint 0805
footprint 0805M
footprint 0805L
pins: 1, 2

## C2012X6S1H105K125AB
designator C?  ValueDisplayed: 1µF  (hidden comment: C2012X6S1H105K125AB)
CAP, CERM, 1 µF, 50 V,+/- 10%, X6S, 0805; Manufacturer: TDK; Polarized: N; CompType: Capacitor; Value: 1uF; U/M: EA; Cap_F: 0.000001; Tolerance_%: 10; ESR_ohm: 0.008782; Value1: 0.008782 ohm; VDC_V: 50; Value2: 50V; IRMS_A: 2.20488; TaMin_C: -55; TaMax_C: 105; Cap_Case: 0805; SizeArea_mm2: 2.5; SizeAreaWB_mm2: 6.75; SizeX_mm: 2; SizeY_mm: 1.25; SizeZ_mm: 1.45; AEC Category: Q200
signal-integrity model Cap
simulation model Cap
footprint 0805_HV
footprint 0805_HV1
footprint 0805
footprint 0805M
footprint 0805L
pins: 1, 2

## C2012X6S1H155K125AB
designator C?  ValueDisplayed: 1.5µF  (hidden comment: C2012X6S1H155K125AB)
CAP, CERM, 1.5 µF, 50 V,+/- 10%, X6S, 0805; Manufacturer: TDK; Polarized: N; CompType: Capacitor; Value: 1.5uF; U/M: EA; Cap_F: 0.0000015; Tolerance_%: 10; ESR_ohm: 0.004574; Value1: 0.004574 ohm; VDC_V: 50; Value2: 50V; IRMS_A: 3.05357; TaMin_C: -55; TaMax_C: 105; Cap_Case: 0805; SizeArea_mm2: 2.5; SizeAreaWB_mm2: 6.75; SizeX_mm: 2; SizeY_mm: 1.25; SizeZ_mm: 1.45; AEC Category: Q200
signal-integrity model Cap
simulation model Cap
footprint 0805_HV
footprint 0805_HV1
footprint 0805
footprint 0805M
footprint 0805L
pins: 1, 2

## C2012X6S1H225K125AB
designator C?  ValueDisplayed: 2.2µF  (hidden comment: C2012X6S1H225K125AB)
CAP, CERM, 2.2 µF, 50 V,+/- 10%, X6S, 0805; Manufacturer: TDK; Polarized: N; CompType: Capacitor; Value: 2.2uF; U/M: EA; Cap_F: 0.0000022; Tolerance_%: 10; ESR_ohm: 0.00366; Value1: 0.00366 ohm; VDC_V: 50; Value2: 50V; IRMS_A: 3.41207; TaMin_C: -55; TaMax_C: 105; Cap_Case: 0805; SizeArea_mm2: 2.5; SizeAreaWB_mm2: 6.75; SizeX_mm: 2; SizeY_mm: 1.25; SizeZ_mm: 1.45; AEC Category: Q200
signal-integrity model Cap
simulation model Cap
footprint 0805_HV
footprint 0805_HV1
footprint 0805
footprint 0805M
footprint 0805L
pins: 1, 2

## C2012X6S1H335K125AC
designator C?  ValueDisplayed: 3.3µF  (hidden comment: C2012X6S1H335K125AC)
CAP, CERM, 3.3 µF, 50 V,+/- 10%, X6S, 0805; Manufacturer: TDK; Polarized: N; CompType: Capacitor; Value: 3.3uF; U/M: EA; Cap_F: 0.0000033; Tolerance_%: 10; ESR_ohm: 0.002798; Value1: 0.002798 ohm; VDC_V: 50; Value2: 50V; IRMS_A: 3.90156; TaMin_C: -55; TaMax_C: 105; Cap_Case: 0805; SizeArea_mm2: 2.5; SizeAreaWB_mm2: 6.75; SizeX_mm: 2; SizeY_mm: 1.25; SizeZ_mm: 1.45; AEC Category: Q200
signal-integrity model Cap
simulation model Cap
footprint 0805_HV
footprint 0805_HV1
footprint 0805
footprint 0805M
footprint 0805L
pins: 1, 2

## C2012X6S1H474K125AB
designator C?  ValueDisplayed: 0.47µF  (hidden comment: C2012X6S1H474K125AB)
CAP, CERM, 0.47 µF, 50 V,+/- 10%, X6S, 0805; Manufacturer: TDK; Polarized: N; CompType: Capacitor; Value: 0.47uF; U/M: EA; Cap_F: 0.00000047; Tolerance_%: 10; ESR_ohm: 0.022012; Value1: 0.022012 ohm; VDC_V: 50; Value2: 50V; IRMS_A: 1.39566; TaMin_C: -55; TaMax_C: 105; Cap_Case: 0805; SizeArea_mm2: 2.5; SizeAreaWB_mm2: 6.75; SizeX_mm: 2; SizeY_mm: 1.25; SizeZ_mm: 1.45; AEC Category: Q200
signal-integrity model Cap
simulation model Cap
footprint 0805_HV
footprint 0805_HV1
footprint 0805
footprint 0805M
footprint 0805L
pins: 1, 2

## C2012X6S1H475K125AC
designator C?  ValueDisplayed: 4.7µF  (hidden comment: C2012X6S1H475K125AC)
CAP, CERM, 4.7 µF, 50 V,+/- 10%, X6S, 0805; Manufacturer: TDK; Polarized: N; CompType: Capacitor; Value: 4.7uF; U/M: EA; Cap_F: 0.0000047; Tolerance_%: 10; ESR_ohm: 0.002346; Value1: 0.002346 ohm; VDC_V: 50; Value2: 50V; IRMS_A: 4.26021; TaMin_C: -55; TaMax_C: 105; Cap_Case: 0805; SizeArea_mm2: 2.5; SizeAreaWB_mm2: 6.75; SizeX_mm: 2; SizeY_mm: 1.25; SizeZ_mm: 1.45; AEC Category: Q200
signal-integrity model Cap
simulation model Cap
footprint 0805_HV
footprint 0805_HV1
footprint 0805
footprint 0805M
footprint 0805L
pins: 1, 2

## C2012X6S1H684K125AB
designator C?  ValueDisplayed: 0.68µF  (hidden comment: C2012X6S1H684K125AB)
CAP, CERM, 0.68 µF, 50 V,+/- 10%, X6S, 0805; Manufacturer: TDK; Polarized: N; CompType: Capacitor; Value: 0.68uF; U/M: EA; Cap_F: 0.00000068; Tolerance_%: 10; ESR_ohm: 0.011711; Value1: 0.011711 ohm; VDC_V: 50; Value2: 50V; IRMS_A: 1.91098; TaMin_C: -55; TaMax_C: 105; Cap_Case: 0805; SizeArea_mm2: 2.5; SizeAreaWB_mm2: 6.75; SizeX_mm: 2; SizeY_mm: 1.25; SizeZ_mm: 1.45; AEC Category: Q200
signal-integrity model Cap
simulation model Cap
footprint 0805_HV
footprint 0805_HV1
footprint 0805
footprint 0805M
footprint 0805L
pins: 1, 2

## C2012X7R0J106M125AB
designator C?  ValueDisplayed: 10µF  (hidden comment: C2012X7R0J106M125AB)
CAP, CERM, 10 µF, 6.3 V,+/- 20%, X7R, 0805; Manufacturer: TDK; Polarized: N; CompType: Capacitor; Value: 10uF; U/M: EA; Cap_F: 0.00001; Tolerance_%: 20; VDC_V: 6.3; Value2: 6.3V; TaMin_C: -55; TaMax_C: 125; Cap_Case: 0805; SizeArea_mm2: 2.5; SizeAreaWB_mm2: 6.75; SizeX_mm: 2; SizeY_mm: 1.25; SizeZ_mm: 1.45; AEC Category: Q200; Green_Lifecycle: Active; Green_REACh: Passed
signal-integrity model Cap
simulation model Cap
footprint 0805_HV
footprint 0805_HV1
footprint 0805
footprint 0805M
footprint 0805L
pins: 1, 2

## C2012X7R1A106K125AC
designator C?  ValueDisplayed: 10µF  (hidden comment: C2012X7R1A106K125AC)
CAP, CERM, 10 µF, 10 V,+/- 10%, X7R, 0805; Manufacturer: TDK; Polarized: N; CompType: Capacitor; Value: 10uF; U/M: EA; Cap_F: 0.00001; Tolerance_%: 10; ESR_ohm: 0.001063; Value1: 0.001063 ohm; Value2: 10V; IRMS_A: 6.32908; TaMin_C: -55; TaMax_C: 125; Cap_Case: 0805; SizeArea_mm2: 2.5; SizeAreaWB_mm2: 6.75; SizeX_mm: 2; SizeY_mm: 1.25; SizeZ_mm: 1.45; AEC Category: Q200; Green_Lifecycle: Active; Green_REACh: Passed
signal-integrity model Cap
simulation model Cap
footprint 0805_HV
footprint 0805_HV1
footprint 0805
footprint 0805M
footprint 0805L
pins: 1, 2

## C2012X7R1A106M125AC
designator C?  ValueDisplayed: 10µF  (hidden comment: C2012X7R1A106M125AC)
CAP, CERM, 10 µF, 10 V,+/- 20%, X7R, 0805; Manufacturer: TDK; Polarized: N; CompType: Capacitor; Value: 10uF; U/M: EA; Cap_F: 0.00001; Tolerance_%: 20; VDC_V: 10; Value2: 10V; TaMin_C: -55; TaMax_C: 125; Cap_Case: 0805; SizeArea_mm2: 2.5; SizeAreaWB_mm2: 6.75; SizeX_mm: 2; SizeY_mm: 1.25; SizeZ_mm: 1.45; AEC Category: Q200; Green_Lifecycle: Not Set; Green_REACh: Incomplete
signal-integrity model Cap
simulation model Cap
footprint 0805_HV
footprint 0805_HV1
footprint 0805
footprint 0805M
footprint 0805L
pins: 1, 2

## C2012X7R1A475M125AC
designator C?  ValueDisplayed: 4.7µF  (hidden comment: C2012X7R1A475M125AC)
CAP, CERM, 4.7 µF, 10 V,+/- 20%, X7R, 0805; Manufacturer: TDK; Polarized: N; CompType: Capacitor; Value: 4.7uF; U/M: EA; Cap_F: 0.0000047; Tolerance_%: 20; VDC_V: 10; Value2: 10V; TaMin_C: -55; TaMax_C: 125; Cap_Case: 0805; SizeArea_mm2: 2.5; SizeAreaWB_mm2: 6.75; SizeX_mm: 2; SizeY_mm: 1.25; SizeZ_mm: 1.45; AEC Category: Q200; Green_Lifecycle: Active; Green_REACh: Passed
signal-integrity model Cap
simulation model Cap
footprint 0805_HV
footprint 0805_HV1
footprint 0805
footprint 0805M
footprint 0805L
pins: 1, 2

## C2012X7R1A685K125AC
designator C?  ValueDisplayed: 6.8µF  (hidden comment: C2012X7R1A685K125AC)
CAP, CERM, 6.8 µF, 10 V,+/- 10%, X7R, 0805; Manufacturer: TDK; Polarized: N; CompType: Capacitor; Value: 6.8uF; U/M: EA; Cap_F: 0.0000068; Tolerance_%: 10; ESR_ohm: 0.002115; Value1: 0.002115 ohm; Value2: 10V; IRMS_A: 4.48596; TaMin_C: -55; TaMax_C: 125; Cap_Case: 0805; SizeArea_mm2: 2.5; SizeAreaWB_mm2: 6.75; SizeX_mm: 2; SizeY_mm: 1.25; SizeZ_mm: 1.45; AEC Category: Q200
signal-integrity model Cap
simulation model Cap
footprint 0805_HV
footprint 0805_HV1
footprint 0805
footprint 0805M
footprint 0805L
pins: 1, 2

## C2012X7R1C225K125AB
designator C?  ValueDisplayed: 2.2µF  (hidden comment: C2012X7R1C225K125AB)
CAP, CERM, 2.2 µF, 16 V,+/- 10%, X7R, 0805; Manufacturer: TDK; Polarized: N; CompType: Capacitor; Value: 2.2uF; U/M: EA; Cap_F: 0.0000022; Tolerance_%: 10; ESR_ohm: 0.0049; Value1: 0.0049 ohm; VDC_V: 16; Value2: 16V; TaMin_C: -55; TaMax_C: 125; Cap_Case: 0805; SizeArea_mm2: 2.5; SizeAreaWB_mm2: 6.75; SizeX_mm: 2; SizeY_mm: 1.25; SizeZ_mm: 1.45; AEC Category: Q200; Green_Lifecycle: Active; Green_REACh: Passed
signal-integrity model Cap
simulation model Cap
footprint 0805_HV
footprint 0805_HV1
footprint 0805
footprint 0805M
footprint 0805L
pins: 1, 2

## C2012X7R1E335K125AB
designator C?  ValueDisplayed: 3.3µF  (hidden comment: C2012X7R1E335K125AB)
CAP, CERM, 3.3 µF, 25 V,+/- 10%, X7R, 0805; Manufacturer: TDK; Polarized: N; CompType: Capacitor; Value: 3.3uF; U/M: EA; Cap_F: 0.0000033; Tolerance_%: 10; VDC_V: 25; Value2: 25V; TaMin_C: -55; TaMax_C: 125; Cap_Case: 0805; SizeArea_mm2: 2.5; SizeAreaWB_mm2: 6.75; SizeX_mm: 2; SizeY_mm: 1.25; SizeZ_mm: 1.45; AEC Category: Q200; Green_Lifecycle: Active; Green_REACh: Passed
signal-integrity model Cap
simulation model Cap
footprint 0805_HV
footprint 0805_HV1
footprint 0805
footprint 0805M
footprint 0805L
pins: 1, 2

## C2012X7R1E474K125AA
designator C?  ValueDisplayed: 0.47µF  (hidden comment: C2012X7R1E474K125AA)
CAP, CERM, 0.47 µF, 25 V,+/- 10%, X7R, 0805; Manufacturer: TDK; Polarized: N; CompType: Capacitor; Value: 0.47uF; U/M: EA; Cap_F: 0.00000047; Tolerance_%: 10; VDC_V: 25; Value2: 25V; TaMin_C: -55; TaMax_C: 125; Cap_Case: 0805; SizeArea_mm2: 2.5; SizeAreaWB_mm2: 6.75; SizeX_mm: 2; SizeY_mm: 1.25; SizeZ_mm: 1.45; AEC Category: Q200; Green_Lifecycle: Active; Green_REACh: Passed
signal-integrity model Cap
simulation model Cap
footprint 0805_HV
footprint 0805_HV1
footprint 0805
footprint 0805M
footprint 0805L
pins: 1, 2

## C2012X7R1E475K125AB
designator C?  ValueDisplayed: 4.7µF  (hidden comment: C2012X7R1E475K125AB)
CAP, CERM, 4.7 µF, 25 V,+/- 10%, X7R, 0805; Manufacturer: TDK; Polarized: N; CompType: Capacitor; Value: 4.7uF; U/M: EA; Cap_F: 0.0000047; Tolerance_%: 10; VDC_V: 25; Value2: 25V; TaMin_C: -55; TaMax_C: 125; Cap_Case: 0805; SizeArea_mm2: 2.5; SizeAreaWB_mm2: 6.75; SizeX_mm: 2; SizeY_mm: 1.25; SizeZ_mm: 1.45; AEC Category: Q200
signal-integrity model Cap
simulation model Cap
footprint 0805_HV
footprint 0805_HV1
footprint 0805
footprint 0805M
footprint 0805L
pins: 1, 2

## C2012X7R1H104K085AA
designator C?  ValueDisplayed: 0.1µF  (hidden comment: C2012X7R1H104K085AA)
CAP, CERM, 0.1 µF, 50 V,+/- 10%, X7R, 0805; Manufacturer: TDK; Polarized: N; CompType: Capacitor; Value: 0.1uF; U/M: EA; Cap_F: 0.0000001; Tolerance_%: 10; ESR_ohm: 0.02619; Value1: 0.02619 ohm; VDC_V: 50; Value2: 50V; IRMS_A: 1.29514; TaMin_C: -55; TaMax_C: 125; Cap_Case: 0805; SizeArea_mm2: 2.5; SizeAreaWB_mm2: 6.75; SizeX_mm: 2; SizeY_mm: 1.25; SizeZ_mm: 1.45; AEC Category: Q200; Green_Lifecycle: NRND; Green_REACh: Passed
signal-integrity model Cap
simulation model Cap
footprint 0805_HV
footprint 0805_HV1
footprint 0805
footprint 0805M
footprint 0805L
pins: 1, 2

## C2012X7R1H105K085AC
designator C?  ValueDisplayed: 1µF  (hidden comment: C2012X7R1H105K085AC)
CAP, CERM, 1 µF, 50 V,+/- 10%, X7R, 0805; Manufacturer: TDK; Polarized: N; CompType: Capacitor; Value: 1uF; U/M: EA; Cap_F: 0.000001; Tolerance_%: 10; VDC_V: 50; Value2: 50V; TaMin_C: -55; TaMax_C: 125; Cap_Case: 0805; SizeArea_mm2: 2.5; SizeAreaWB_mm2: 6.75; SizeX_mm: 2; SizeY_mm: 1.25; SizeZ_mm: 1.45; AEC Category: Q200; Green_Lifecycle: Not Set; Green_REACh: Incomplete
signal-integrity model Cap
simulation model Cap
footprint 0805_HV
footprint 0805_HV1
footprint 0805
footprint 0805M
footprint 0805L
pins: 1, 2

## C2012X7R1H105K125AB
designator C?  ValueDisplayed: 1µF  (hidden comment: C2012X7R1H105K125AB)
CAP, CERM, 1 µF, 50 V,+/- 10%, X7R, 0805; Manufacturer: TDK; Polarized: N; CompType: Capacitor; Value: 1uF; U/M: EA; Cap_F: 0.000001; Tolerance_%: 10; ESR_ohm: 0.008782; Value1: 0.008782 ohm; VDC_V: 50; Value2: 50V; IRMS_A: 2.20488; TaMin_C: -55; TaMax_C: 125; Cap_Case: 0805; SizeArea_mm2: 2.5; SizeAreaWB_mm2: 6.75; SizeX_mm: 2; SizeY_mm: 1.25; SizeZ_mm: 1.45; AEC Category: Q200; Green_Lifecycle: Active; Green_REACh: Passed
signal-integrity model Cap
simulation model Cap
footprint 0805_HV
footprint 0805_HV1
footprint 0805
footprint 0805M
footprint 0805L
pins: 1, 2

## C2012X7R1H154K125AA
designator C?  ValueDisplayed: 0.15µF  (hidden comment: C2012X7R1H154K125AA)
CAP, CERM, 0.15 µF, 50 V,+/- 10%, X7R, 0805; Manufacturer: TDK; Polarized: N; CompType: Capacitor; Value: 0.15uF; U/M: EA; Cap_F: 0.00000015; Tolerance_%: 10; ESR_ohm: 0.019115; Value1: 0.019115 ohm; VDC_V: 50; Value2: 50V; IRMS_A: 1.50852; TaMin_C: -55; TaMax_C: 125; Cap_Case: 0805; SizeArea_mm2: 2.5; SizeAreaWB_mm2: 6.75; SizeX_mm: 2; SizeY_mm: 1.25; SizeZ_mm: 1.45; AEC Category: Q200
signal-integrity model Cap
simulation model Cap
footprint 0805_HV
footprint 0805_HV1
footprint 0805
footprint 0805M
footprint 0805L
pins: 1, 2

## C2012X7R1H155K125AC
designator C?  ValueDisplayed: 1.5µF  (hidden comment: C2012X7R1H155K125AC)
CAP, CERM, 1.5 µF, 50 V,+/- 10%, X7R, 0805; Manufacturer: TDK; Polarized: N; CompType: Capacitor; Value: 1.5uF; U/M: EA; Cap_F: 0.0000015; Tolerance_%: 10; ESR_ohm: 0.004574; Value1: 0.004574 ohm; VDC_V: 50; Value2: 50V; IRMS_A: 3.05357; TaMin_C: -55; TaMax_C: 125; Cap_Case: 0805; SizeArea_mm2: 2.5; SizeAreaWB_mm2: 6.75; SizeX_mm: 2; SizeY_mm: 1.25; SizeZ_mm: 1.45; AEC Category: Q200
signal-integrity model Cap
simulation model Cap
footprint 0805_HV
footprint 0805_HV1
footprint 0805
footprint 0805M
footprint 0805L
pins: 1, 2

## C2012X7R1H224K125AA
designator C?  ValueDisplayed: 0.22µF  (hidden comment: C2012X7R1H224K125AA)
CAP, CERM, 0.22 µF, 50 V,+/- 10%, X7R, 0805; Manufacturer: TDK; Polarized: N; CompType: Capacitor; Value: 0.22uF; U/M: EA; Cap_F: 0.00000022; Tolerance_%: 10; ESR_ohm: 0.016949; Value1: 0.016949 ohm; VDC_V: 50; Value2: 50V; IRMS_A: 1.59611; TaMin_C: -55; TaMax_C: 125; Cap_Case: 0805; SizeArea_mm2: 2.5; SizeAreaWB_mm2: 6.75; SizeX_mm: 2; SizeY_mm: 1.25; SizeZ_mm: 1.45; AEC Category: Q200; Green_Lifecycle: Active; Green_REACh: Passed
signal-integrity model Cap
simulation model Cap
footprint 0805_HV
footprint 0805_HV1
footprint 0805
footprint 0805M
footprint 0805L
pins: 1, 2

## C2012X7R1H225K125AC
designator C?  ValueDisplayed: 2.2µF  (hidden comment: C2012X7R1H225K125AC)
CAP, CERM, 2.2 µF, 50 V,+/- 10%, X7R, 0805; Manufacturer: TDK; Polarized: N; CompType: Capacitor; Value: 2.2uF; U/M: EA; Cap_F: 0.0000022; Tolerance_%: 10; ESR_ohm: 0.00366; Value1: 0.00366 ohm; VDC_V: 50; Value2: 50V; IRMS_A: 3.41207; TaMin_C: -55; TaMax_C: 125; Cap_Case: 0805; SizeArea_mm2: 2.5; SizeAreaWB_mm2: 6.75; SizeX_mm: 2; SizeY_mm: 1.25; SizeZ_mm: 1.45; AEC Category: Q200; Green_Lifecycle: Active; Green_REACh: Passed
signal-integrity model Cap
simulation model Cap
footprint 0805_HV
footprint 0805_HV1
footprint 0805
footprint 0805M
footprint 0805L
pins: 1, 2

## C2012X7R1H225M125AC
designator C?  ValueDisplayed: 2.2µF  (hidden comment: C2012X7R1H225M125AC)
CAP, CERM, 2.2 µF, 50 V,+/- 20%, X7R, 0805; Manufacturer: TDK; Polarized: N; CompType: Capacitor; Value: 2.2uF; U/M: EA; Cap_F: 0.0000022; Tolerance_%: 20; VDC_V: 50; Value2: 50V; TaMin_C: -55; TaMax_C: 125; Cap_Case: 0805; SizeArea_mm2: 2.5; SizeAreaWB_mm2: 6.75; SizeX_mm: 2; SizeY_mm: 1.25; SizeZ_mm: 1.45; AEC Category: Q200; Green_Lifecycle: Not Set; Green_REACh: Incomplete
signal-integrity model Cap
simulation model Cap
footprint 0805_HV
footprint 0805_HV1
footprint 0805
footprint 0805M
footprint 0805L
pins: 1, 2

## C2012X7R1H334K125AA
designator C?  ValueDisplayed: 0.33µF  (hidden comment: C2012X7R1H334K125AA)
CAP, CERM, 0.33 µF, 50 V,+/- 10%, X7R, 0805; Manufacturer: TDK; Polarized: N; CompType: Capacitor; Value: 0.33uF; U/M: EA; Cap_F: 0.00000033; Tolerance_%: 10; ESR_ohm: 0.012274; Value1: 0.012274 ohm; VDC_V: 50; Value2: 50V; IRMS_A: 1.87147; TaMin_C: -55; TaMax_C: 125; Cap_Case: 0805; SizeArea_mm2: 2.5; SizeAreaWB_mm2: 6.75; SizeX_mm: 2; SizeY_mm: 1.25; SizeZ_mm: 1.45; AEC Category: Q200; Green_Lifecycle: Active; Green_REACh: Passed
signal-integrity model Cap
simulation model Cap
footprint 0805_HV
footprint 0805_HV1
footprint 0805
footprint 0805M
footprint 0805L
pins: 1, 2

## C2012X7R1H474K125AB
designator C?  ValueDisplayed: 0.47µF  (hidden comment: C2012X7R1H474K125AB)
CAP, CERM, 0.47 µF, 50 V,+/- 10%, X7R, 0805; Manufacturer: TDK; Polarized: N; CompType: Capacitor; Value: 0.47uF; U/M: EA; Cap_F: 0.00000047; Tolerance_%: 10; ESR_ohm: 0.022012; Value1: 0.022012 ohm; VDC_V: 50; Value2: 50V; IRMS_A: 1.39566; TaMin_C: -55; TaMax_C: 125; Cap_Case: 0805; SizeArea_mm2: 2.5; SizeAreaWB_mm2: 6.75; SizeX_mm: 2; SizeY_mm: 1.25; SizeZ_mm: 1.45; AEC Category: Q200
signal-integrity model Cap
simulation model Cap
footprint 0805_HV
footprint 0805_HV1
footprint 0805
footprint 0805M
footprint 0805L
pins: 1, 2

## C2012X7R1H684K125AB
designator C?  ValueDisplayed: 0.68µF  (hidden comment: C2012X7R1H684K125AB)
CAP, CERM, 0.68 µF, 50 V,+/- 10%, X7R, 0805; Manufacturer: TDK; Polarized: N; CompType: Capacitor; Value: 0.68uF; U/M: EA; Cap_F: 0.00000068; Tolerance_%: 10; ESR_ohm: 0.011711; Value1: 0.011711 ohm; VDC_V: 50; Value2: 50V; IRMS_A: 1.91098; TaMin_C: -55; TaMax_C: 125; Cap_Case: 0805; SizeArea_mm2: 2.5; SizeAreaWB_mm2: 6.75; SizeX_mm: 2; SizeY_mm: 1.25; SizeZ_mm: 1.45; AEC Category: Q200
signal-integrity model Cap
simulation model Cap
footprint 0805_HV
footprint 0805_HV1
footprint 0805
footprint 0805M
footprint 0805L
pins: 1, 2

## C2012X7R1H684M125AB
designator C?  ValueDisplayed: 0.68µF  (hidden comment: C2012X7R1H684M125AB)
CAP, CERM, 0.68 µF, 50 V,+/- 20%, X7R, 0805; Manufacturer: TDK; Polarized: N; CompType: Capacitor; Value: 0.68uF; U/M: EA; Cap_F: 0.00000068; Tolerance_%: 20; VDC_V: 50; Value2: 50V; TaMin_C: -55; TaMax_C: 125; Cap_Case: 0805; SizeArea_mm2: 2.5; SizeAreaWB_mm2: 6.75; SizeX_mm: 2; SizeY_mm: 1.25; SizeZ_mm: 1.45; AEC Category: Q200
signal-integrity model Cap
simulation model Cap
footprint 0805_HV
footprint 0805_HV1
footprint 0805
footprint 0805M
footprint 0805L
pins: 1, 2

## C2012X7R1V225K085AC
designator C?  ValueDisplayed: 2.2µF  (hidden comment: C2012X7R1V225K085AC)
CAP, CERM, 2.2 µF, 35 V,+/- 10%, X7R, 0805; Manufacturer: TDK; Polarized: N; CompType: Capacitor; Value: 2.2uF; U/M: EA; Cap_F: 0.0000022; Tolerance_%: 10; VDC_V: 35; Value2: 35V; TaMin_C: -55; TaMax_C: 125; Cap_Case: 0805; SizeArea_mm2: 2.5; SizeAreaWB_mm2: 6.75; SizeX_mm: 2; SizeY_mm: 1.25; SizeZ_mm: 1.45; AEC Category: Q200
signal-integrity model Cap
simulation model Cap
footprint 0805_HV
footprint 0805_HV1
footprint 0805
footprint 0805M
footprint 0805L
pins: 1, 2

## C2012X7R1V335K125AC
designator C?  ValueDisplayed: 3.3µF  (hidden comment: C2012X7R1V335K125AC)
CAP, CERM, 3.3 µF, 35 V,+/- 10%, X7R, 0805; Manufacturer: TDK; Polarized: N; CompType: Capacitor; Value: 3.3uF; U/M: EA; Cap_F: 0.0000033; Tolerance_%: 10; ESR_ohm: 0.002798; Value1: 0.002798 ohm; VDC_V: 35; Value2: 35V; IRMS_A: 3.90156; TaMin_C: -55; TaMax_C: 125; Cap_Case: 0805; SizeArea_mm2: 2.5; SizeAreaWB_mm2: 6.75; SizeX_mm: 2; SizeY_mm: 1.25; SizeZ_mm: 1.45; AEC Category: Q200
signal-integrity model Cap
simulation model Cap
footprint 0805_HV
footprint 0805_HV1
footprint 0805
footprint 0805M
footprint 0805L
pins: 1, 2

## C2012X7R1V475K125AC
designator C?  ValueDisplayed: 4.7µF  (hidden comment: C2012X7R1V475K125AC)
CAP, CERM, 4.7 µF, 35 V,+/- 10%, X7R, 0805; Manufacturer: TDK; Polarized: N; CompType: Capacitor; Value: 4.7uF; U/M: EA; Cap_F: 0.0000047; Tolerance_%: 10; ESR_ohm: 0.002346; Value1: 0.002346 ohm; VDC_V: 35; Value2: 35V; IRMS_A: 4.26021; TaMin_C: -55; TaMax_C: 125; Cap_Case: 0805; SizeArea_mm2: 2.5; SizeAreaWB_mm2: 6.75; SizeX_mm: 2; SizeY_mm: 1.25; SizeZ_mm: 1.45; AEC Category: Q200
signal-integrity model Cap
simulation model Cap
footprint 0805_HV
footprint 0805_HV1
footprint 0805
footprint 0805M
footprint 0805L
pins: 1, 2

## C2012X7R2A104K125AA
designator C?  ValueDisplayed: 0.1µF  (hidden comment: C2012X7R2A104K125AA)
CAP, CERM, 0.1 µF, 100 V,+/- 10%, X7R, 0805; Manufacturer: TDK; Polarized: N; CompType: Capacitor; Value: 0.1uF; U/M: EA; Cap_F: 0.0000001; Tolerance_%: 10; ESR_ohm: 0.020726; Value1: 0.020726 ohm; VDC_V: 100; Value2: 100V; IRMS_A: 1.456; TaMin_C: -55; TaMax_C: 125; Cap_Case: 0805; SizeArea_mm2: 2.5; SizeAreaWB_mm2: 6.75; SizeX_mm: 2; SizeY_mm: 1.25; SizeZ_mm: 1.45; AEC Category: Q200; Green_Lifecycle: Active; Green_REACh: Passed
signal-integrity model Cap
simulation model Cap
footprint 0805_HV
footprint 0805_HV1
footprint 0805
footprint 0805M
footprint 0805L
pins: 1, 2

## C2012X7R2A473K125AA
designator C?  ValueDisplayed: 0.047µF  (hidden comment: C2012X7R2A473K125AA)
CAP, CERM, 0.047 µF, 100 V,+/- 10%, X7R, 0805; Manufacturer: TDK; Polarized: N; CompType: Capacitor; Value: 0.047uF; U/M: EA; Cap_F: 0.000000047; Tolerance_%: 10; ESR_ohm: 0.049089; Value1: 0.049089 ohm; VDC_V: 100; Value2: 100V; IRMS_A: 0.963171; TaMin_C: -55; TaMax_C: 125; Cap_Case: 0805; SizeArea_mm2: 2.5; SizeAreaWB_mm2: 6.75; SizeX_mm: 2; SizeY_mm: 1.25; SizeZ_mm: 1.45; AEC Category: Q200
signal-integrity model Cap
simulation model Cap
footprint 0805_HV
footprint 0805_HV1
footprint 0805
footprint 0805M
footprint 0805L
pins: 1, 2

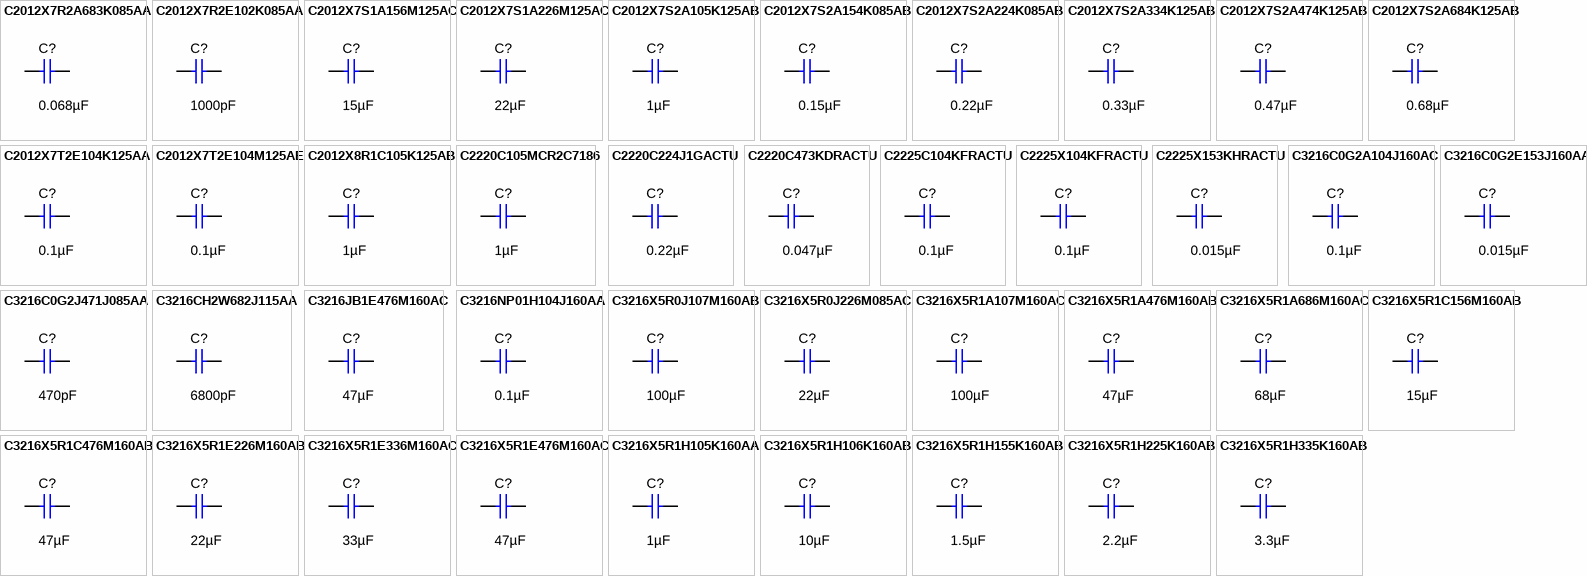
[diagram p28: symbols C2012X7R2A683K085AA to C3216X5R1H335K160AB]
